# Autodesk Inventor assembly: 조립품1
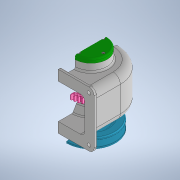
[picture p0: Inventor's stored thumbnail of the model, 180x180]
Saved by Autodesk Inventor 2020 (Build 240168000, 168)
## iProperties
Created: 2022-09
Part Number: 조립품1
Document SubType Name: Assembly
Designer: Administrator
Author: Administrator
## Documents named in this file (16)
- C:\Users\Administrator\Desktop\720906V1012\답안조립품.iam
- C:\Users\Administrator\Desktop\720906V1012\본체.ipt
- C:\Users\Administrator\Desktop\720906V1012\축.ipt
- C:\Users\Administrator\Desktop\720906V1012\키 6 x 6 x 22.ipt
- C:\Users\Administrator\Desktop\720906V1012\스퍼기어.ipt
- C:\Users\Administrator\Desktop\720906V1012\칼라.ipt
- C:\Users\Administrator\Desktop\720906V1012\베어링 6203.ipt
- C:\Users\Administrator\Desktop\720906V1012\앞커버.ipt
- C:\Users\Administrator\Desktop\720906V1012\뒤커버.ipt
- C:\Users\Administrator\Desktop\720906V1012\오일 실 17 x 30 x 8.ipt
- C:\Users\Administrator\Desktop\720906V1012\볼트 M3 x 10.ipt
- C:\Users\Administrator\Desktop\720906V1012\키 5 x 5 x 18.ipt
- C:\Users\Administrator\Desktop\720906V1012\V-벨트풀리.ipt
- C:\Users\Administrator\Desktop\720906V1012\멈춤나사 M4 x 10.ipt
- C:\Users\Administrator\Desktop\720906V1012\와셔 6 x 22.ipt
- C:\Users\Administrator\Desktop\720906V1012\육각머리볼트 M3 x 8.ipt
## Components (9 placed, 2 different names)
1. V-벨트풀리:1 — 각도:2
2. ISO 4762 M3 x 10:1
3. ISO 4762 M3 x 10:2
4. ISO 4762 M3 x 10:3
5. ISO 4762 M3 x 10:4
6. ISO 4762 M3 x 10:5
7. ISO 4762 M3 x 10:6
8. ISO 4762 M3 x 10:7
9. ISO 4762 M3 x 10:8
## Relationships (1: Angle 1)
- 각도:2 [Angle]: V-벨트풀리:1
